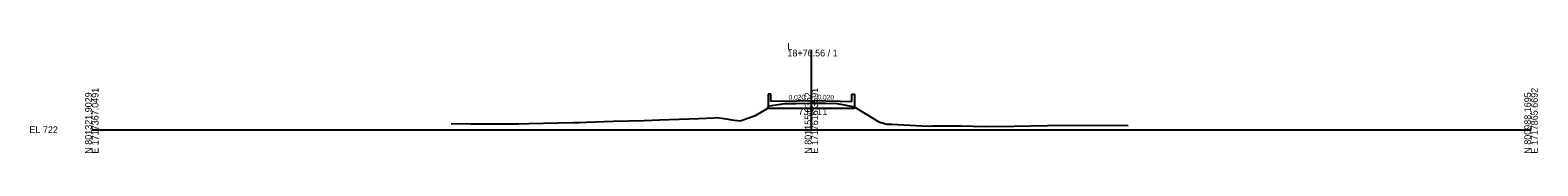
# Model space of a CAD drawing. Extents: x 974 to 5203, y -10 to 9544.
# Drawn here: x 4574 to 5203, y 490 to 536 of the extents above; entities that cross this region are included whole.
import ezdxf

# ---------------------------------------------------------------- set-up
doc = ezdxf.new("R2010")
doc.units = 0
for name, color, linetype in [('Exist Cross Section Cell', 7, 'Continuous'), ('Exist XS Center Line Elevation Label', 7, 'Continuous'), ('Exist XS Ground Line', 7, 'Continuous'), ('Prop XS Bridge', 7, 'Continuous'), ('Prop XS Dump Level', 7, 'Continuous'), ('Prop XS SE Text', 7, 'Continuous')]:
    doc.layers.add(name, color=color, linetype=linetype)

msp = doc.modelspace()

# ---------------------------------------------------------------- linework, layer by layer
at = {"layer": 'Exist Cross Section Cell'}
for p, q in [((4900, 500), (4900, 533.37)), ((4600, 500), (4900, 500)), ((4900, 500), (5200, 500))]:
    msp.add_line(p, q, dxfattribs=at)
at = {"layer": 'Exist XS Ground Line'}
for p, q in [((4881.38, 508.78), (4882.25, 509.92)), ((4882.25, 509.92), (4883.43, 510.05)), ((4883.43, 510.05), (4888.98, 510.88)), ((4888.98, 510.88), (4893.64, 511)), ((4893.64, 511), (4899.5, 511.12)), ((4899.5, 511.12), (4900, 511.11)), ((4900, 511.11), (4905.81, 511.02)), ((4905.81, 511.02), (4910.78, 510.95)), ((4910.78, 510.95), (4917.92, 509.61)), ((4917.92, 509.61), (4918.56, 509.1)), ((4782.13, 502.59), (4800.66, 503.05)), ((4800.66, 503.05), (4803.23, 503.07)), ((4803.23, 503.07), (4806.19, 503.2)), ((4806.19, 503.2), (4817.39, 503.52)), ((4817.39, 503.52), (4830.26, 503.92)), ((4830.26, 503.92), (4836.62, 504.15)), ((4836.62, 504.15), (4853.01, 504.63)), ((4853.01, 504.63), (4859.28, 505.01)), ((4859.28, 505.01), (4860.47, 505.15)), ((4860.47, 505.15), (4861.72, 504.91)), ((4861.72, 504.91), (4863.51, 504.73)), ((4863.51, 504.73), (4864.63, 504.49)), ((4864.63, 504.49), (4866.77, 504.18)), ((4866.77, 504.18), (4870.34, 503.73)), ((4870.34, 503.73), (4876.73, 505.91)), ((4876.73, 505.91), (4881.38, 508.78)), ((4918.56, 509.1), (4928.11, 503.35)), ((4928.11, 503.35), (4928.91, 503.08)), ((4928.91, 503.08), (4931.61, 502.33)), ((4749.89, 502.58), (4758.06, 502.42)), ((4758.06, 502.42), (4764.71, 502.5)), ((4764.71, 502.5), (4777.83, 502.49)), ((4777.83, 502.49), (4782.13, 502.59)), ((4931.61, 502.33), (4933.57, 502.37)), ((4933.57, 502.37), (4946, 501.6)), ((4946, 501.6), (4949.03, 501.55)), ((4949.03, 501.55), (4950.59, 501.57)), ((4950.59, 501.57), (4962.56, 501.65)), ((4962.56, 501.65), (4972.1, 501.32)), ((4972.1, 501.32), (4984.39, 501.44)), ((4984.39, 501.44), (4998.41, 501.84)), ((4998.41, 501.84), (5006.59, 501.93)), ((5006.59, 501.93), (5032.1, 501.75))]:
    msp.add_line(p, q, dxfattribs=at)
at = {"layer": 'Prop XS Bridge'}
for p, q in [((4882, 514.83), (4882, 511.83)), ((4883.08, 514.83), (4882, 514.83)), ((4882, 511.83), (4882, 508.86)), ((4883.08, 511.83), (4883.08, 514.83)), ((4888, 511.93), (4883.08, 511.83)), ((4888, 511.93), (4900, 512.17)), ((4900, 512.17), (4912, 511.93)), ((4912, 511.93), (4916.92, 511.83)), ((4916.92, 511.83), (4916.92, 514.83)), ((4916.92, 514.83), (4918, 514.83)), ((4918, 514.83), (4918, 511.83)), ((4918, 511.83), (4918, 508.86)), ((4918, 508.86), (4882, 508.86))]:
    msp.add_line(p, q, dxfattribs=at)
at = {"layer": 'Prop XS Dump Level'}
for p, q in [((4888, 511.93), (4900, 512.17)), ((4900, 512.17), (4912, 511.93))]:
    msp.add_line(p, q, dxfattribs=at)

# ---------------------------------------------------------------- texts
at = {"layer": 'Exist Cross Section Cell'}
for s, p in [('L', (4890, 533.37)), ('18+76.56 / 1', (4890, 530.57)), ('EL 722', (4574, 498.6))]:
    msp.add_text(s, height=2.8, dxfattribs=at).set_placement(p)
for s, p in [('N 801321.9029', (4600, 490)), ('E 1717367.0491', (4602.8, 490)), ('N 801155.0362', (4900, 490)), ('E 1717616.3591', (4902.8, 490)), ('N 800988.1695', (5200, 490)), ('E 1717865.6692', (5202.8, 490))]:
    msp.add_text(s, height=2.8, rotation=90, dxfattribs=at).set_placement(p)
at = {"layer": 'Exist XS Center Line Elevation Label'}
msp.add_text('733.11', height=3, dxfattribs=at).set_placement((4894.47, 506.11))
at = {"layer": 'Prop XS SE Text'}
for rotation, p in [(1.14576, (4890.49, 512.48)), (358.85424, (4902.49, 512.62))]:
    msp.add_text('0.020', height=2, rotation=rotation, dxfattribs=at).set_placement(p)

doc.saveas('drawing.dxf')
